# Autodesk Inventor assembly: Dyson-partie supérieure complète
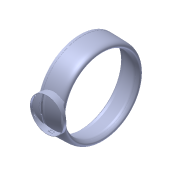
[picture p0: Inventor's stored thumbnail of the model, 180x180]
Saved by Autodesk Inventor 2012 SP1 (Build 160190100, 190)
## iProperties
Created: 2012-11
Part Number: Dyson-partie supérieure complète
Document SubType Name: Assembly
Designer: Administrateur
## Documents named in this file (3)
- D:\Cours\1-Cours-2013-14\Dropbox\1SI\1. Besoin\Dyson\Composants importés\Dyson Air Multiplier-Assemblage final\Dyson-partie supérieure complète.iam
- D:\Cours\1-Cours-2013-14\Dropbox\1SI\1. Besoin\Dyson\Composants importés\Dyson Air Multiplier-Assemblage final\Dyson-Partie supérieure 1.ipt
- D:\Cours\1-Cours-2013-14\Dropbox\1SI\1. Besoin\Dyson\Composants importés\Dyson Air Multiplier-Assemblage final\Dyson-Partie supérieure 2.ipt
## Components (2 placed, 2 different names)
1. Dyson-Partie supérieure 1:1
2. Dyson-Partie supérieure 2:1
